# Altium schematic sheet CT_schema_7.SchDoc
size 423 x 414 mm
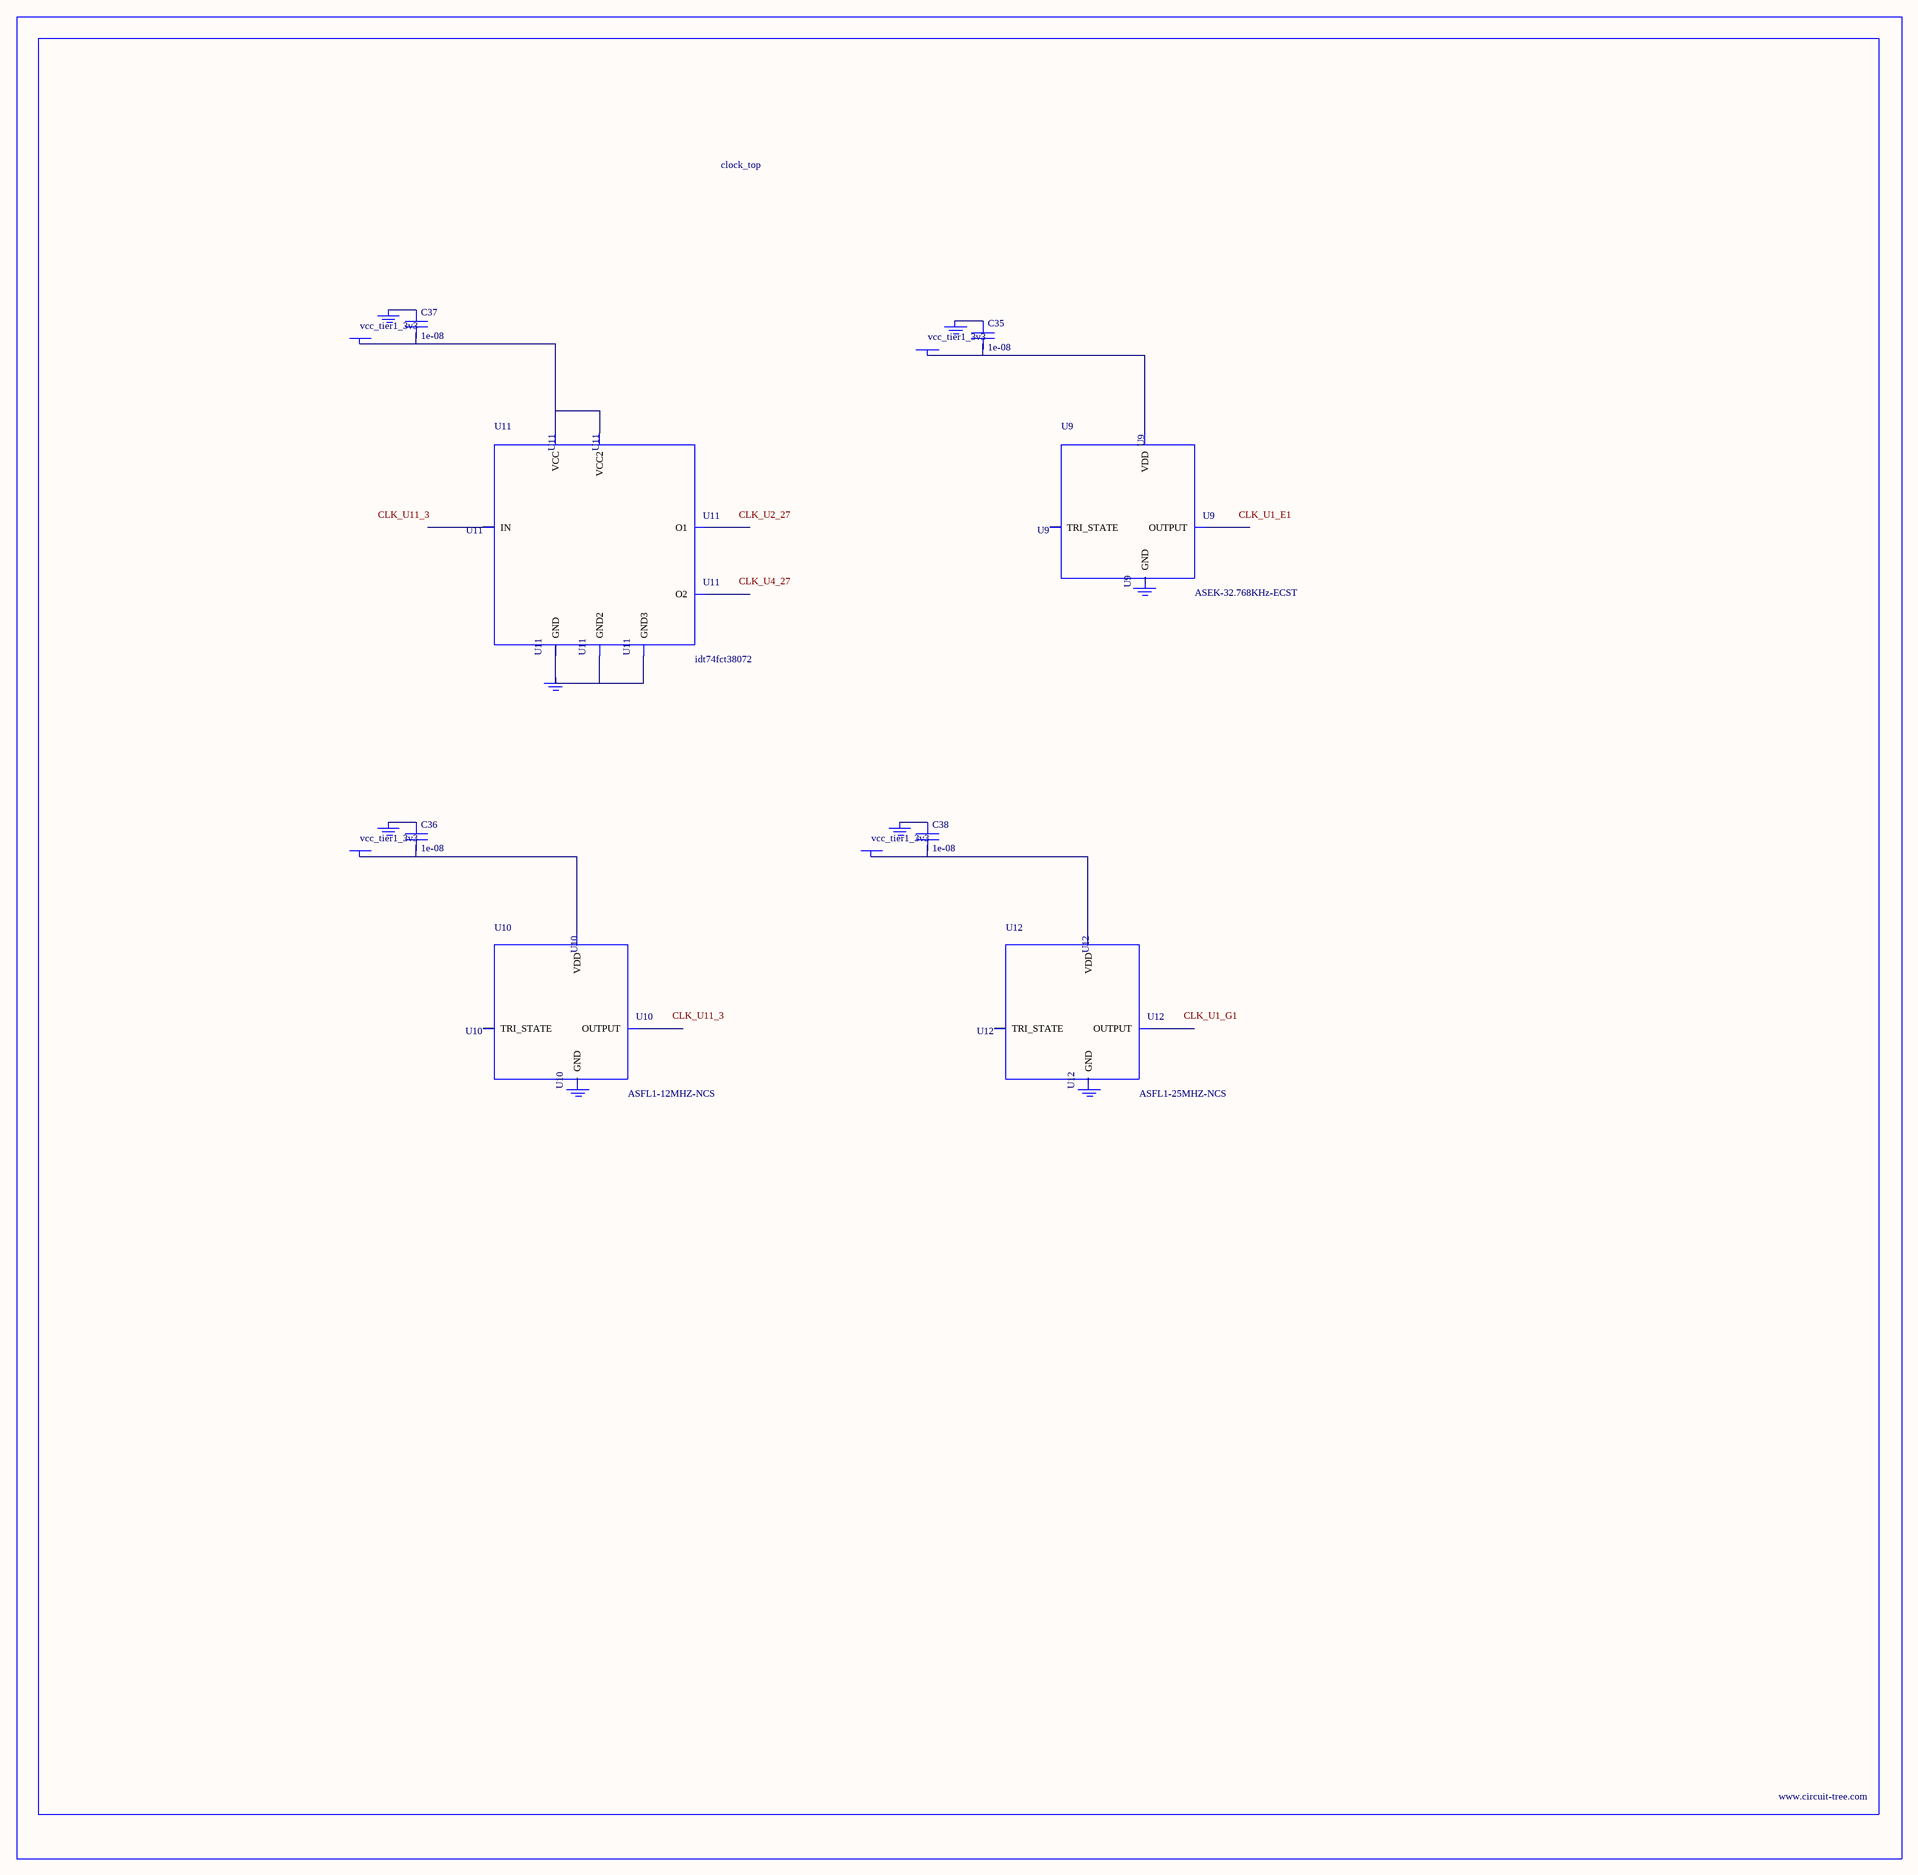
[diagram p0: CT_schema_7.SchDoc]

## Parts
BORDER6  (no value)
C35  1e-08  [C0402]
C36  1e-08  [C0402]
C37  1e-08  [C0402]
C38  1e-08  [C0402]
GND_INSTANCE_6_0  (no value)
GND_INSTANCE_6_1  (no value)
GND_INSTANCE_6_2  (no value)
GND_INSTANCE_6_3  (no value)
GND_INSTANCE_6_4  (no value)
GND_INSTANCE_6_5  (no value)
GND_INSTANCE_6_6  (no value)
GND_INSTANCE_6_7  (no value)
POWER_INSTANCE_6_0  vcc_tier1_3v3
POWER_INSTANCE_6_1  vcc_tier1_3v3
POWER_INSTANCE_6_2  vcc_tier1_3v3
POWER_INSTANCE_6_3  vcc_tier1_3v3
U9  ASEK-32.768KHz-ECST  [ASEK]
U10  ASFL1-12MHZ-NCS  [ASFL1]
U11  idt74fct38072  [IDT74FCT38072]
U12  ASFL1-25MHZ-NCS  [ASFL1]

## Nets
NetC35_1: C35.1 GND_INSTANCE_6_0.0(GND)
NetC35_2: C35.2 POWER_INSTANCE_6_0.0(PWR) U9.4(VDD)
NetC36_1: C36.1 GND_INSTANCE_6_2.0(GND)
NetC36_2: C36.2 POWER_INSTANCE_6_1.0(PWR) U10.4(VDD)
NetC37_1: C37.1 GND_INSTANCE_6_4.0(GND)
NetC37_2: C37.2 POWER_INSTANCE_6_2.0(PWR) U11.1(VCC) U11.2(VCC2)
NetC38_1: C38.1 GND_INSTANCE_6_6.0(GND)
NetC38_2: C38.2 POWER_INSTANCE_6_3.0(PWR) U12.4(VDD)
NetGND_INSTANCE_6_5_0: GND_INSTANCE_6_5.0(GND) U11.4(GND) U11.5(GND2) U11.8(GND3)

Not connected (* = marked no-connect by the designer): GND_INSTANCE_6_1 0(GND); GND_INSTANCE_6_3 0(GND); GND_INSTANCE_6_7 0(GND); U9 1(TRI_STATE) 2(GND) 3(OUTPUT); U10 1(TRI_STATE) 2(GND) 3(OUTPUT); U11 3(IN) 6(O2) 7(O1); U12 1(TRI_STATE) 2(GND) 3(OUTPUT)

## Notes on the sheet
- Labels drawn without touching a wire or pin: CLK_U1_E1, CLK_U1_G1, CLK_U2_27, CLK_U4_27, CLK_U11_3

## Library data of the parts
BORDER6 = BORDER_PAGE6
C35-C38 = C0402C103K3RAC
GND_INSTANCE_6_0-GND_INSTANCE_6_7 = GND
POWER_INSTANCE_6_0-POWER_INSTANCE_6_3 = PWR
